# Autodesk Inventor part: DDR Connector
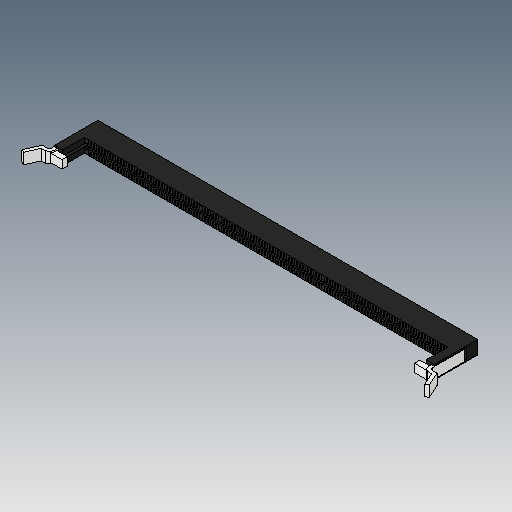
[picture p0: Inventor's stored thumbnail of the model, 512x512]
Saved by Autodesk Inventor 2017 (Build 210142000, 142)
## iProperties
Created: 2005-11
Part Number: DDR Connector
Material: Generic
Document SubType Name: Modeling
Designer: DanielSeverino
Density: 1 g/cm^3
Appearance: Default
Author: DanielSeverino
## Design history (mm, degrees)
feature "Solid1"
body "Solid2"
